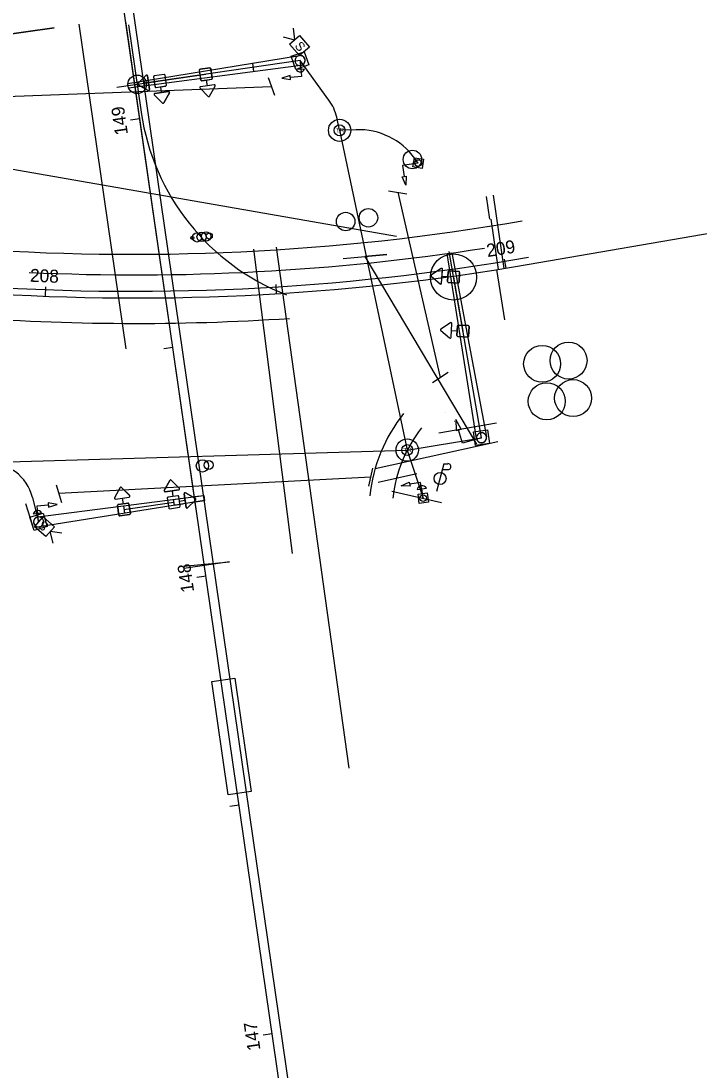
# Model space of a CAD drawing. Extents: x 1827063 to 1831280, y 711192 to 712800.
# Drawn here: x 1828633.8 to 1828780.5, y 711406.9 to 711633.8 of the extents above; entities that cross this region are included whole.
import ezdxf

# ---------------------------------------------------------------- set-up
doc = ezdxf.new("R2010")
doc.units = 0
for name, color, linetype in [('BR_P_Beam_Object', 7, 'Continuous'), ('BR_P_Gen_Joint_Filler', 7, 'Continuous'), ('BR_P_Sub_Centerline', 7, 'Continuous'), ('BR_X_Sub_Object', 7, 'Continuous'), ('Default', 7, 'Continuous'), ('DR_P_Cells', 7, 'Continuous'), ('DR_P_Storm_Sewer', 7, 'Continuous'), ('PM_P_Crosswalk', 7, 'Continuous'), ('PV_P_Walk', 7, 'Continuous'), ('PV_X_EOP', 7, 'Continuous'), ('SG_P_Foundation', 7, 'Continuous'), ('SG_P_Interconnect_Cable', 7, 'Continuous'), ('SG_P_Wiring', 7, 'Continuous'), ('SG_X_Messenger_Wire', 7, 'Continuous'), ('UT_P_Water', 7, 'Continuous'), ('UT_X_Electric_Cells', 7, 'Continuous')]:
    doc.layers.add(name, color=color, linetype=linetype)

# ---------------------------------------------------------------- blocks, each defined once
blk = doc.blocks.new('A$C140F1C83')
at = {"layer": 'Default'}
for p, q in [((-14.7, 81.2), (38.7, 115.7)), ((57.7, 46.4), (-13.7, 72.8)), ((22, 59.6), (11, 29.8)), ((45.8, 113.1), (63.9, 52.2)), ((-20.4, 36.3), (-39.1, -14.3)), ((36.3, 20.4), (-14.3, 39.1)), ((20.4, -36.3), (39.1, 14.3)), ((46.4, -57.7), (72.8, 13.7)), ((81.2, 14.7), (115.7, -38.7)), ((-36.3, -20.4), (14.3, -39.1)), ((59.6, -22), (29.8, -11)), ((113.1, -45.8), (52.2, -63.9))]:
    blk.add_line(p, q, dxfattribs=at)
for centre, start, end in [((41.2, 111.7), 16.6041, 122.86431), ((-12.1, 77.2), 122.86431, 249.7342), ((-16, 34.7), 69.7342, 159.7342), ((34.7, 16), 339.7342, 69.7342), ((59.4, 50.8), 249.7342, 16.6041), ((77.2, 12.1), 32.86431, 159.7342), ((-34.7, -16), 159.7342, 249.7342), ((16, -34.7), 249.7342, 339.7342), ((111.7, -41.2), 286.6041, 32.86431), ((50.8, -59.4), 159.7342, 286.6041)]:
    blk.add_arc(centre, 4.76, start, end, dxfattribs=at)
blk = doc.blocks.new('SPOLE_1')
at = {"layer": 'Default'}
blk.add_circle((0, 0), 0.0138, dxfattribs=at)
blk = doc.blocks.new('A$C258B21FD')
at = {"layer": 'Default'}
for p, q in [((1.209, 0.609), (1.307, 1.09)), ((1.307, 1.09), (1.431, 0.61)), ((1.431, 0.61), (1.209, 0.609))]:
    blk.add_line(p, q, dxfattribs=at)
for points in [[(1.431, 0.61), (1.209, 0.609), (1.307, 1.09), (1.431, 0.61)], [(0.442, 0), (1.32, -0.003), (1.32, 0.609)]]:
    blk.add_lwpolyline(points, dxfattribs=at)
blk = doc.blocks.new('Sighead')
at = {"layer": 'Default'}
for p, q in [((-0.03, 0.975), (-0.335, 0.569)), ((0.335, 0.569), (0.03, 0.975)), ((-0.305, 0.508), (0.305, 0.508)), ((0, 0.508), (0, 0.254)), ((-0.254, -0.216), (-0.254, 0.216)), ((-0.216, 0.254), (0.216, 0.254)), ((0.254, 0.216), (0.254, -0.216)), ((0.216, -0.254), (-0.216, -0.254))]:
    blk.add_line(p, q, dxfattribs=at)
for centre, start, end in [((0, 0.953), 36.8699, 143.1301), ((-0.305, 0.546), 143.1301, 270), ((0.305, 0.546), 270, 36.8699), ((-0.216, 0.216), 90, 180), ((0.216, 0.216), 0, 90), ((-0.216, -0.216), 180, 270), ((0.216, -0.216), 270, 0)]:
    blk.add_arc(centre, 0.0381, start, end, dxfattribs=at)
blk = doc.blocks.new('A$C70A22DE5')
at = {"layer": 'Default'}
for p, q in [((0, 0), (0.476, 0)), ((0.476, 0.236), (0.476, -0.236))]:
    blk.add_line(p, q, dxfattribs=at)
blk.add_arc((0.369, 0), 0.259, 294.3601, 65.6399, dxfattribs=at)

msp = doc.modelspace()

# ---------------------------------------------------------------- linework, layer by layer
at = {"layer": 'BR_P_Beam_Object'}
for p, q in [((1828656.9, 711620.3), (1828694.04, 711626.31)), ((1828694.35, 711624.15), (1828657.04, 711619.29)), ((1828657.04, 711619.29), (1828656.9, 711620.3)), ((1828726.02, 711583.46), (1828727.02, 711583.63)), ((1828727.02, 711583.63), (1828734.54, 711543.84)), ((1828732.39, 711543.47), (1828726.02, 711583.46)), ((1828637.47, 711526.52), (1828673.34, 711531.17)), ((1828673.49, 711530.07), (1828637.78, 711524.36)), ((1828673.34, 711531.17), (1828673.49, 711530.07))]:
    msp.add_line(p, q, dxfattribs=at)
for centre, start, end in [((1828694.19, 711625.23), 278.3396, 98.3396), ((1828733.46, 711543.66), 189.8881, 9.8881), ((1828637.62, 711525.44), 98.2621, 278.2621)]:
    msp.add_arc(centre, 1.09, start, end, dxfattribs=at)
at = {"layer": 'BR_P_Gen_Joint_Filler'}
for centre in [(1828746.58, 711559.63), (1828752.29, 711560.33), (1828747.57, 711551.52), (1828753.28, 711552.22)]:
    msp.add_circle(centre, 4, dxfattribs=at)
at = {"layer": 'BR_P_Sub_Centerline'}
for centre, radius in [((1828702.76, 711610.14), 2.42), ((1828702.76, 711610.14), 1.18), ((1828717.38, 711540.98), 2.42), ((1828717.38, 711540.98), 1.18)]:
    msp.add_circle(centre, radius, dxfattribs=at)
at = {"layer": 'BR_X_Sub_Object'}
for p, q in [((1828692.73, 711632.23), (1828693.02, 711629.7)), ((1828690.57, 711630.38), (1828693.02, 711629.7)), ((1828642.62, 711523.02), (1828640.1, 711523.33)), ((1828640.75, 711520.87), (1828640.1, 711523.33)), ((1828675.12, 711490.94), (1828680.06, 711491.67)), ((1828678.67, 711466.44), (1828675.12, 711490.94)), ((1828680.06, 711491.67), (1828683.61, 711467.15)), ((1828683.61, 711467.15), (1828678.67, 711466.44))]:
    msp.add_line(p, q, dxfattribs=at)
for points in [[(1828694.1, 711630.62), (1828696.21, 711628.15), (1828694.04, 711626.3), (1828691.94, 711628.78)], [(1828639.16, 711522.26), (1828636.71, 711524.39), (1828638.58, 711526.54), (1828641.03, 711524.4)]]:
    msp.add_lwpolyline(points, close=True, dxfattribs=at)
at = {"layer": 'DR_P_Cells'}
for points in [[(1828720.92, 711603.88), (1828720.6, 711601.91), (1828718.62, 711602.23), (1828718.95, 711604.21)], [(1828719.72, 711531.43), (1828721.7, 711531.71), (1828721.99, 711529.73), (1828720, 711529.45)]]:
    msp.add_lwpolyline(points, close=True, dxfattribs=at)
for centre in [(1828719.77, 711603.06), (1828720.85, 711530.58)]:
    msp.add_circle(centre, 0.727, dxfattribs=at)
at = {"layer": 'DR_P_Storm_Sewer'}
for p, q in [((1828720.42, 711192.02), (1828611.37, 711945.24)), ((1828743.76, 711581.16), (1829022.78, 711629.35)), ((1828659.52, 711612.64), (1828657.54, 711612.35)), ((1828738.79, 711580.33), (1828738.47, 711582.3)), ((1828689.12, 711574.8), (1828688.99, 711576.79)), ((1828639.14, 711574.25), (1828639.22, 711576.25)), ((1828666.68, 711563.15), (1828664.71, 711562.87)), ((1828673.85, 711513.67), (1828671.87, 711513.38)), ((1828681.01, 711464.18), (1828679.03, 711463.9)), ((1828688.18, 711414.7), (1828686.2, 711414.41))]:
    msp.add_line(p, q, dxfattribs=at)
msp.add_arc((1828658.72, 712073.54), 499.67, 265.6226, 279.7988, dxfattribs=at)
at = {"layer": 'PM_P_Crosswalk'}
for p, q in [((1828641.01, 711632.32), (1828628, 711630.45)), ((1828628, 711630.45), (1828641.01, 711632.32)), ((1828683.91, 711624.59), (1828684.13, 711622.9)), ((1828735.99, 711596.08), (1828738.28, 711580.25)), ((1828735.47, 711590.94), (1828737.05, 711580.05)), ((1828727.57, 711547.21), (1828727.58, 711547.23)), ((1828732.85, 711546.97), (1828732.85, 711546.97)), ((1828634.8, 711529.44), (1828636.29, 711524.67)), ((1828666.76, 711530.32), (1828668.75, 711530.58)), ((1828666.76, 711530.32), (1828666.94, 711529.06)), ((1828666.95, 711529.03), (1828668.92, 711529.34)), ((1828671.35, 711530.92), (1828673.34, 711531.17)), ((1828671.52, 711529.76), (1828673.49, 711530.07)), ((1828655.98, 711528.92), (1828656.21, 711527.34))]:
    msp.add_line(p, q, dxfattribs=at)
msp.add_circle((1828718.51, 711603.83), 2, dxfattribs=at)
for radius in [495.67, 503.67]:
    msp.add_arc((1828657.93, 712078.99), radius, 265.6226, 279.7988, dxfattribs=at)
at = {"layer": 'PV_P_Walk'}
for p, q in [((1828722.4, 711192.31), (1828579.11, 712181.99)), ((1828671.75, 711528.13), (1828656.47, 711633.7)), ((1828694.19, 711625.23), (1828660.55, 711620.32)), ((1828654.56, 711619.44), (1828673.79, 711622.25)), ((1828657.04, 711619.29), (1828656.9, 711620.3)), ((1828660.48, 711620.82), (1828660.63, 711619.82)), ((1828733.46, 711543.65), (1828726.45, 711583.94)), ((1828703.49, 711582.43), (1828713, 711583.26)), ((1828713, 711583.26), (1828708.24, 711582.85)), ((1828708.24, 711582.85), (1828732.37, 711542.28)), ((1828727.41, 711578.41), (1828729.45, 711566.71)), ((1828724.24, 711544.69), (1828736.7, 711546.9)), ((1828737.02, 711542.79), (1828710.43, 711536.9)), ((1828719.46, 711535.83), (1828711.08, 711533.97)), ((1828714.06, 711532.06), (1828724.78, 711529.65)), ((1828656.09, 711528.13), (1828666.85, 711529.69)), ((1828668.98, 711515.89), (1828678.96, 711516.77)), ((1828678.96, 711516.77), (1828669.06, 711515.33))]:
    msp.add_line(p, q, dxfattribs=at)
for centre, radius in [((1828658.95, 711620.08), 2), ((1828708.99, 711591.22), 2), ((1828704.06, 711590.41), 2), ((1828672.89, 711587.08), 1), ((1828673.88, 711587.19), 1), ((1828670.9, 711586.88), 0.333), ((1828671.89, 711586.98), 1), ((1828674.54, 711587.25), 0.667), ((1828727.41, 711578.41), 5), ((1828673.08, 711537.56), 1.33), ((1828674.41, 711537.74), 1)]:
    msp.add_circle(centre, radius, dxfattribs=at)
for radius in [34.5, 29.5]:
    msp.add_arc((1828743.6, 711527.43), radius, 141.5641, 173.9267, dxfattribs=at)
at = {"layer": 'PV_X_EOP'}
for p, q in [((1828646.29, 711633.09), (1828656.52, 711562.88)), ((1828657.09, 711632.94), (1828659.82, 711614.03)), ((1828688.71, 711617.7), (1828687.38, 711621.47)), ((1828626.11, 711617.27), (1828688.04, 711619.59)), ((1828713.35, 711597.08), (1828717.29, 711596.43)), ((1828715.32, 711596.75), (1828724.53, 711556.71)), ((1828692.59, 711518.64), (1828684.2, 711584.45)), ((1828689.06, 711584.83), (1828704.72, 711472.15)), ((1828738.51, 711569.14), (1828736.79, 711580.01)), ((1828722.85, 711555.62), (1828726.21, 711557.8)), ((1828709.07, 711533.18), (1828709.96, 711537.08)), ((1828709.51, 711535.13), (1828642.02, 711531.58)), ((1828641.44, 711533.49), (1828642.59, 711529.66))]:
    msp.add_line(p, q, dxfattribs=at)
for centre, radius, start, end in [((1828709.31, 711621.19), 50, 188.238, 248.8774), ((1828658.72, 712073.54), 494.67, 267.3183, 278.7644), ((1828658.72, 712073.54), 505.17, 265.6226, 273.77)]:
    msp.add_arc(centre, radius, start, end, dxfattribs=at)
at = {"layer": 'SG_P_Foundation'}
for p, q in [((1828692.28, 711626.15), (1828695.11, 711627.15)), ((1828695.11, 711627.15), (1828696.11, 711624.32)), ((1828693.28, 711623.32), (1828692.28, 711626.15)), ((1828696.11, 711624.32), (1828693.28, 711623.32)), ((1828731.76, 711544.92), (1828734.73, 711545.35)), ((1828732.19, 711541.95), (1828731.76, 711544.92)), ((1828734.73, 711545.35), (1828735.16, 711542.38)), ((1828735.16, 711542.38), (1828732.19, 711541.95)), ((1828635.74, 711526.43), (1828638.61, 711527.32)), ((1828638.61, 711527.32), (1828639.5, 711524.45)), ((1828636.64, 711523.56), (1828635.74, 711526.43)), ((1828639.5, 711524.45), (1828636.64, 711523.56))]:
    msp.add_line(p, q, dxfattribs=at)
for centre, start, end in [((1828694.19, 711625.23), 109.4742, 289.4742), ((1828694.19, 711625.23), 289.4742, 109.4742), ((1828733.46, 711543.65), 98.238, 278.238), ((1828733.46, 711543.65), 278.238, 98.238), ((1828637.62, 711525.44), 17.3105, 197.3105), ((1828637.62, 711525.44), 197.3105, 17.3105)]:
    msp.add_arc(centre, 1.09, start, end, dxfattribs=at)
at = {"layer": 'SG_P_Interconnect_Cable'}
for p, q in [((1828702.76, 711610.14), (1828717.38, 711540.98)), ((1828734.5, 711595.84), (1828735.21, 711590.89)), ((1828623.06, 711538.18), (1828717.38, 711540.98))]:
    msp.add_line(p, q, dxfattribs=at)
at = {"layer": 'SG_P_Wiring'}
for p, q in [((1828700.44, 711616.68), (1828694.19, 711625.23)), ((1828702.76, 711610.14), (1828702.13, 711612.95)), ((1828706.36, 711610.27), (1828702.76, 711610.14)), ((1828719.77, 711603.06), (1828719.04, 711604.07)), ((1828726.02, 711583.46), (1828727.02, 711583.63)), ((1828725.66, 711549.04), (1828725.66, 711549.04)), ((1828717.38, 711540.98), (1828733.46, 711543.65)), ((1828717.38, 711540.98), (1828720.85, 711530.58))]:
    msp.add_line(p, q, dxfattribs=at)
msp.add_lwpolyline([(1828636.28, 711530.73), (1828637.62, 711525.44)], dxfattribs=at)
for centre, radius, start, end in [((1828692.37, 711610.78), 10, 12.5383, 36.1505), ((1828706.89, 711595.27), 15, 35.8764, 92.0234), ((1828626.59, 711528.28), 10, 14.2206, 91.6412)]:
    msp.add_arc(centre, radius, start, end, dxfattribs=at)
at = {"layer": 'SG_X_Messenger_Wire'}
msp.add_line((1828598.06, 711607.67), (1828715.04, 711587.28), dxfattribs=at)
at = {"layer": 'UT_P_Water'}
for p, q in [((1828672.4, 711623.12), (1828672.7, 711621.02)), ((1828674.66, 711623.64), (1828672.56, 711623.34)), ((1828675.18, 711621.38), (1828674.87, 711623.48)), ((1828662.77, 711618.12), (1828662.77, 711618.12)), ((1828665.13, 711619.72), (1828665.13, 711619.72)), ((1828672.56, 711619.24), (1828674.33, 711617.48)), ((1828674.63, 711617.52), (1828675.82, 711619.72)), ((1828724.72, 711580.22), (1828722.63, 711578.85)), ((1828728.55, 711579.59), (1828726.43, 711579.72)), ((1828728.6, 711577.27), (1828728.73, 711579.39)), ((1828722.61, 711578.55), (1828724.52, 711576.93)), ((1828726.28, 711577.22), (1828728.4, 711577.09)), ((1828726.75, 711568.53), (1828724.67, 711567.15)), ((1828730.59, 711567.9), (1828728.46, 711568.02)), ((1828730.63, 711565.58), (1828730.76, 711567.7)), ((1828724.65, 711566.85), (1828726.55, 711565.23)), ((1828728.31, 711565.53), (1828730.43, 711565.4)), ((1828655.26, 711532.86), (1828654.06, 711530.67)), ((1828657.33, 711531.14), (1828655.56, 711532.9)), ((1828667.98, 711532.38), (1828667.98, 711532.38)), ((1828657.48, 711527.26), (1828657.18, 711529.36)), ((1828665.62, 711530.78), (1828665.62, 711530.78)), ((1828654.7, 711529.01), (1828655.01, 711526.9)), ((1828655.22, 711526.74), (1828657.32, 711527.05))]:
    msp.add_line(p, q, dxfattribs=at)
for points in [[(1828664.77, 711622.2), (1828662.66, 711621.89)], [(1828660.89, 711622.04), (1828659.12, 711620.27)], [(1828659.17, 711619.97), (1828661.36, 711618.77)], [(1828661.64, 711618.96), (1828661.21, 711621.93), (1828661.21, 711621.93)], [(1828662.51, 711621.68), (1828662.81, 711619.58)], [(1828665.28, 711619.93), (1828664.98, 711622.04)], [(1828675.63, 711619.99), (1828674.15, 711619.78), (1828672.66, 711619.56)], [(1828672.92, 711620.86), (1828673.97, 711621.02), (1828675.02, 711621.17)], [(1828662.66, 711617.8), (1828664.43, 711616.03)], [(1828665.74, 711618.55), (1828662.77, 711618.12), (1828662.77, 711618.12)], [(1828663.02, 711619.42), (1828665.13, 711619.72), (1828665.13, 711619.72)], [(1828664.73, 711616.08), (1828665.93, 711618.27)], [(1828724.83, 711577.06), (1828724.92, 711578.56), (1828725.01, 711580.05)], [(1828726.23, 711579.54), (1828726.17, 711578.48), (1828726.1, 711577.42)], [(1828726.86, 711565.37), (1828726.95, 711566.86), (1828727.04, 711568.36)], [(1828728.27, 711567.85), (1828728.2, 711566.79), (1828728.14, 711565.73)], [(1828666.02, 711534.42), (1828664.82, 711532.23)], [(1828668.09, 711532.7), (1828666.32, 711534.46)], [(1828665.01, 711531.95), (1828667.98, 711532.38), (1828667.98, 711532.38)], [(1828669.11, 711531.53), (1828669.54, 711528.56), (1828669.54, 711528.56)], [(1828671.58, 711530.52), (1828669.39, 711531.72)], [(1828654.25, 711530.39), (1828655.74, 711530.61), (1828657.22, 711530.82)], [(1828656.97, 711529.52), (1828655.92, 711529.37), (1828654.86, 711529.22)], [(1828665.46, 711530.56), (1828665.77, 711528.46)], [(1828667.73, 711531.08), (1828665.62, 711530.78), (1828665.62, 711530.78)], [(1828668.24, 711528.82), (1828667.94, 711530.92)], [(1828669.86, 711528.46), (1828671.63, 711530.22)], [(1828665.98, 711528.3), (1828668.08, 711528.6)]]:
    msp.add_lwpolyline(points, dxfattribs=at)
for centre, start, end in [((1828661.02, 711621.91), 8.238, 135.1079), ((1828664.79, 711622.01), 8.238, 98.238), ((1828672.59, 711623.15), 98.238, 188.238), ((1828674.69, 711623.46), 8.238, 98.238), ((1828659.26, 711620.14), 135.1079, 241.3681), ((1828662.69, 711621.71), 98.238, 188.238), ((1828665.1, 711619.91), 278.238, 8.238), ((1828672.89, 711621.05), 188.238, 278.238), ((1828674.99, 711621.35), 278.238, 8.238), ((1828675.66, 711619.81), 331.3681, 98.238), ((1828661.45, 711618.94), 241.3681, 8.238), ((1828662.8, 711617.93), 98.238, 225.1079), ((1828663, 711619.6), 188.238, 278.238), ((1828665.76, 711618.36), 331.3681, 98.238), ((1828672.69, 711619.38), 98.238, 225.1079), ((1828664.57, 711616.17), 225.1079, 331.3681), ((1828674.46, 711617.61), 225.1079, 331.3681), ((1828724.82, 711580.07), 356.5278, 123.3977), ((1828726.42, 711579.53), 86.5278, 176.5278), ((1828728.54, 711579.4), 356.5278, 86.5278), ((1828722.74, 711578.69), 123.3977, 229.6579), ((1828724.64, 711577.07), 229.6579, 356.5278), ((1828726.29, 711577.41), 176.5278, 266.5278), ((1828728.41, 711577.28), 266.5278, 356.5278), ((1828726.86, 711568.37), 356.5278, 123.3977), ((1828728.45, 711567.84), 86.5278, 176.5278), ((1828730.57, 711567.71), 356.5278, 86.5278), ((1828724.77, 711567), 123.3977, 229.6579), ((1828726.68, 711565.38), 229.6579, 356.5278), ((1828728.32, 711565.72), 176.5278, 266.5278), ((1828730.45, 711565.59), 266.5278, 356.5278), ((1828666.19, 711534.33), 45.0501, 151.3103), ((1828655.43, 711532.77), 45.0501, 151.3103), ((1828664.99, 711532.14), 151.3103, 278.1802), ((1828667.96, 711532.56), 278.1802, 45.0501), ((1828669.3, 711531.56), 61.3103, 188.1802), ((1828654.23, 711530.58), 151.3103, 278.1802), ((1828654.89, 711529.03), 98.1802, 188.1802), ((1828656.99, 711529.34), 8.1802, 98.1802), ((1828657.2, 711531.01), 278.1802, 45.0501), ((1828665.65, 711530.59), 98.1802, 188.1802), ((1828667.75, 711530.89), 8.1802, 98.1802), ((1828671.49, 711530.36), 315.0501, 61.3103), ((1828655.19, 711526.93), 188.1802, 278.1802), ((1828657.3, 711527.23), 278.1802, 8.1802), ((1828665.95, 711528.49), 188.1802, 278.1802), ((1828668.06, 711528.79), 278.1802, 8.1802), ((1828669.73, 711528.59), 188.1802, 315.0501)]:
    msp.add_arc(centre, 0.187, start, end, dxfattribs=at)
at = {"layer": 'UT_X_Electric_Cells'}
for p, q in [((1828725.34, 711538.03), (1828723.74, 711532.03)), ((1828725, 711536.76), (1828726.19, 711536.76)), ((1828725.34, 711538.03), (1828726.19, 711538.03))]:
    msp.add_line(p, q, dxfattribs=at)
msp.add_circle((1828724.49, 711534.83), 1.3, dxfattribs=at)
msp.add_arc((1828726.2, 711537.4), 0.638, 268.8767, 91.1233, dxfattribs=at)

# ---------------------------------------------------------------- block references
at = {"layer": 'BR_X_Sub_Object'}
for p, xscale, yscale, rotation in [((1828694.19, 711625.23), 3.941724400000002, 3.9417243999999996, -87.86015094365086), ((1828720.85, 711530.58), 4.301251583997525, 4.301251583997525, 99.31394319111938), ((1828637.62, 711525.44), 3.9417244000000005, 3.9417244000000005, 98.23796141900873)]:
    msp.add_blockref('A$C70A22DE5', p, dxfattribs=dict(at, xscale=xscale, yscale=yscale, rotation=rotation))
at = {"layer": 'DR_P_Cells'}
for p, xscale, yscale, rotation in [((1828719.77, 711603.06), 52.49554118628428, 52.495541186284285, -99.33968427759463), ((1828720.85, 711530.58), 52.49554118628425, 52.49554118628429, 8.065986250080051)]:
    msp.add_blockref('SPOLE_1', p, dxfattribs=dict(at, xscale=xscale, yscale=yscale, rotation=rotation))
at = {"layer": 'UT_P_Water'}
for name, p, xscale, yscale, rotation in [('A$C258B21FD', (1828694.03, 711626.97), 3.937000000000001, -3.9369999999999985, -84.658455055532), ('A$C140F1C83', (1828663.89, 711620.81), 0.039369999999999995, 0.039369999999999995, -151.49624301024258), ('Sighead', (1828673.79, 711622.25), 4.921250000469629, 4.921250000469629, -171.76203856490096), ('A$C258B21FD', (1828721.49, 711603.34), 3.9370000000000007, 3.936999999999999, -170.64833106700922), ('Sighead', (1828727.41, 711578.41), 4.92125000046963, 4.92125000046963, 86.52776606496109), ('Sighead', (1828729.45, 711566.71), 4.92125000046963, 4.92125000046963, 86.52776606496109), ('A$C258B21FD', (1828735.54, 711544.25), 4.896847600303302, -4.8968476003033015, -163.9288545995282), ('A$C140F1C83', (1828666.85, 711529.69), 0.03937, 0.03936999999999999, 28.445974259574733), ('A$C258B21FD', (1828721.15, 711528.86), 3.937000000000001, 3.9369999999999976, 99.64442448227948), ('Sighead', (1828656.09, 711528.13), 4.921250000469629, 4.921250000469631, 8.18017870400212), ('A$C258B21FD', (1828637.78, 711523.71), 3.9369999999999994, -3.9369999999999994, 95.0573478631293)]:
    msp.add_blockref(name, p, dxfattribs=dict(at, xscale=xscale, yscale=yscale, rotation=rotation))

# ---------------------------------------------------------------- texts
at = {"layer": 'BR_P_Sub_Centerline'}
for p in [(1828701.99, 711609.61), (1828716.61, 711540.45)]:
    msp.add_text('TR', height=0.962, rotation=3.7551, dxfattribs=at).set_placement(p)
at = {"layer": 'BR_X_Sub_Object'}
for rotation, p in [(310.4023, (1828692.91, 711628.33)), (138.9131, (1828640, 711524.71))]:
    msp.add_text('S', height=1.95, rotation=rotation, dxfattribs=at).set_placement(p)
at = {"layer": 'DR_P_Storm_Sewer'}
for s, rotation, p in [('149', 98.238, (1828656.97, 711609.3)), ('209', 9.2206, (1828734.76, 711582.71)), ('208', 357.7539, (1828635.71, 711577.39)), ('148', 98.238, (1828671.29, 711510.37)), ('147', 98.238, (1828685.64, 711411.28))]:
    msp.add_text(s, height=2.8, rotation=rotation, dxfattribs=at).set_placement(p)

doc.saveas('drawing.dxf')
